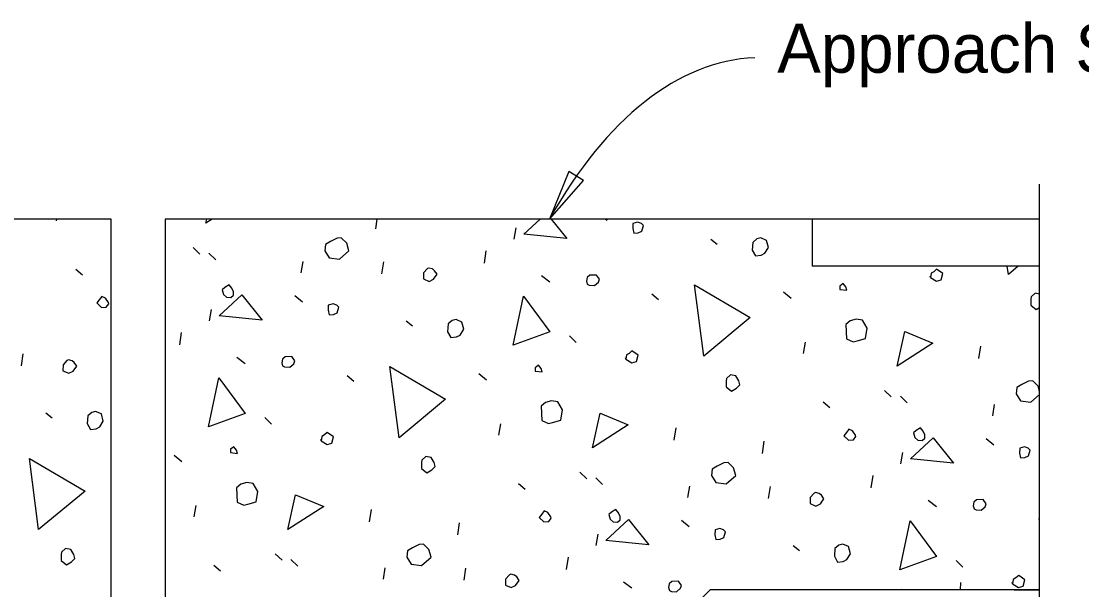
# Model space of a CAD drawing. Extents: x 0 to 30.8, y 0 to 21.2.
# Drawn here: x 25.516 to 28.795, y 17.529 to 19.286 of the extents above; entities that cross this region are included whole.
import ezdxf

# ---------------------------------------------------------------- set-up
doc = ezdxf.new("R2010")
doc.units = 0
for name, color, linetype in [('Dimension', 7, 'Continuous'), ('Miscellaneous', 7, 'Continuous'), ('SupstrConc', 7, 'Continuous'), ('TextStructures', 7, 'Continuous')]:
    doc.layers.add(name, color=color, linetype=linetype)

msp = doc.modelspace()

# ---------------------------------------------------------------- linework, layer by layer
at = {"layer": 'Dimension'}
msp.add_lwpolyline([(27.1495, 18.6746), (27.2542, 18.7936), (27.2091, 18.8214)], close=True, dxfattribs=at)
msp.add_lwpolyline([(28.6643, 15.7565), (28.6643, 16.023), (28.7418, 16.023), (28.6643, 16.0567), (28.5868, 16.0905), (28.6643, 16.0905), (28.6643, 18.7825)], dxfattribs=at)
msp.add_ellipse((27.8946, 16.8059), major_axis=(0.1111, -2.3674), ratio=0.464296, start_param=3.141604, end_param=3.781059, dxfattribs=at)
at = {"layer": 'Miscellaneous'}
for p, q in [((25.6248, 18.669), (25.6258, 18.6747)), ((26.6119, 18.6449), (26.6162, 18.6747)), ((27.3224, 18.6747), (27.327, 18.6708)), ((28.6643, 18.6747), (27.9607, 18.6747)), ((27.04, 18.612), (27.046, 18.6473)), ((27.6482, 18.612), (27.6679, 18.5965)), ((26.0477, 18.5869), (26.0686, 18.5666)), ((26.0965, 18.5689), (26.1175, 18.5486)), ((26.9484, 18.5383), (26.9539, 18.576)), ((26.3819, 18.5082), (26.388, 18.5435)), ((26.6312, 18.5051), (26.6366, 18.5428)), ((25.6855, 18.5196), (25.7058, 18.5018)), ((27.1243, 18.5001), (27.1501, 18.4811)), ((26.3619, 18.4381), (26.3853, 18.4185)), ((27.4655, 18.4439), (27.4858, 18.4261)), ((27.8729, 18.4496), (27.8963, 18.43)), ((26.0982, 18.3597), (26.1043, 18.395)), ((26.7064, 18.3596), (26.7261, 18.3442)), ((26.0066, 18.286), (26.0121, 18.3237)), ((27.2105, 18.3135), (27.2315, 18.2933)), ((27.9343, 18.259), (27.9404, 18.2943)), ((28.4767, 18.2439), (28.4821, 18.2815)), ((25.5171, 18.2209), (25.5225, 18.2586)), ((26.1825, 18.2477), (26.2083, 18.2287)), ((26.9311, 18.1972), (26.9545, 18.1776)), ((26.5237, 18.1916), (26.544, 18.1737)), ((28.1849, 18.145), (28.2058, 18.1247)), ((27.9951, 18.1096), (28.0154, 18.0918)), ((28.2337, 18.127), (28.2546, 18.1067)), ((28.5191, 18.0663), (28.5252, 18.1016)), ((25.5923, 18.0754), (25.612, 18.0599)), ((26.2688, 18.0612), (26.2897, 18.0409)), ((26.9925, 18.0066), (26.9986, 18.0419)), ((27.5349, 17.9915), (27.5404, 18.0292)), ((27.8073, 17.9506), (27.8127, 17.9883)), ((28.4991, 17.9962), (28.5225, 17.9766)), ((25.9893, 17.9449), (26.0127, 17.9253)), ((28.2354, 17.9178), (28.2415, 17.9531)), ((27.2431, 17.8926), (27.2641, 17.8723)), ((27.2919, 17.8746), (27.3129, 17.8544)), ((28.1438, 17.8441), (28.1493, 17.8818)), ((27.0533, 17.8573), (27.0736, 17.8394)), ((27.5773, 17.8139), (27.5834, 17.8492)), ((27.8266, 17.8109), (27.8321, 17.8485)), ((28.3197, 17.8058), (28.3455, 17.7868)), ((26.0508, 17.7543), (26.0568, 17.7896)), ((26.5932, 17.7392), (26.5986, 17.7769)), ((27.5573, 17.7439), (27.5807, 17.7242)), ((28.6609, 17.7497), (28.6643, 17.7467)), ((26.8655, 17.6983), (26.871, 17.736)), ((27.2936, 17.6654), (27.2997, 17.7007)), ((26.3013, 17.6403), (26.3223, 17.62)), ((27.9019, 17.6654), (27.9215, 17.6499)), ((26.3501, 17.6223), (26.3711, 17.602)), ((27.2021, 17.5917), (27.2075, 17.6294)), ((28.406, 17.6193), (28.4269, 17.599)), ((26.1115, 17.6049), (26.1318, 17.5871)), ((26.6356, 17.5616), (26.6416, 17.5969)), ((26.8849, 17.5585), (26.8903, 17.5962)), ((27.378, 17.5535), (27.4038, 17.5345)), ((28.5856, 17.5289), (28.6643, 17.5289))]:
    msp.add_line(p, q, dxfattribs=at)
for points in [[(26.087, 18.6621), (26.0898, 18.6747)], [(26.1067, 18.6747), (26.087, 18.6621)], [(27.0694, 18.6277), (27.12, 18.6747)], [(27.1545, 18.6747), (27.2025, 18.6142), (27.0694, 18.6277)], [(27.4063, 18.6455), (27.4102, 18.631), (27.4229, 18.6318), (27.4343, 18.6375), (27.4401, 18.6546), (27.4333, 18.6605), (27.4217, 18.6652), (27.4072, 18.6613), (27.4063, 18.6455)], [(26.4542, 18.5767), (26.4679, 18.5545), (26.5001, 18.5502), (26.5294, 18.5762), (26.5229, 18.6003), (26.5056, 18.6164), (26.4929, 18.6156), (26.4725, 18.6049), (26.4569, 18.5956), (26.4542, 18.5767)], [(27.7775, 18.6026), (27.7761, 18.5789), (27.7861, 18.5609), (27.8037, 18.563), (27.8151, 18.5687), (27.8257, 18.5871), (27.8199, 18.6088), (27.8022, 18.617), (27.7901, 18.6137), (27.7775, 18.6026)], [(26.7597, 18.5085), (26.7594, 18.4903), (26.7771, 18.4821), (26.791, 18.4884), (26.8022, 18.5043), (26.7942, 18.5151), (26.7874, 18.5211), (26.7765, 18.5233), (26.7716, 18.522), (26.7597, 18.5085)], [(28.5676, 18.5037), (28.5644, 18.5289)], [(28.5981, 18.5289), (28.5676, 18.5037)], [(27.2661, 18.4733), (27.2722, 18.4698), (27.288, 18.4689), (27.3005, 18.48), (27.3034, 18.4885), (27.2947, 18.5017), (27.2741, 18.5014), (27.2657, 18.494), (27.2635, 18.483), (27.2661, 18.4733)], [(28.327, 18.4936), (28.3453, 18.483), (28.3598, 18.4869), (28.365, 18.5064), (28.3459, 18.5194), (28.3376, 18.512), (28.3286, 18.507), (28.327, 18.4936), (28.3257, 18.4984)], [(26.1411, 18.4411), (26.1509, 18.4334), (26.1643, 18.4318), (26.1727, 18.4392), (26.1725, 18.4495), (26.1668, 18.4609), (26.1588, 18.4717), (26.1456, 18.463), (26.1372, 18.4556), (26.1411, 18.4411)], [(27.6258, 18.2514), (27.5978, 18.4716), (27.7699, 18.3702), (27.6258, 18.2514)], [(28.0468, 18.4574), (28.0681, 18.4553), (28.0655, 18.465), (28.0574, 18.4757), (28.0466, 18.4677), (28.0468, 18.4574)], [(25.7497, 18.4152), (25.7639, 18.4009), (25.779, 18.4024), (25.7868, 18.4122), (25.7855, 18.417), (25.7768, 18.4302), (25.7651, 18.4349), (25.7574, 18.425), (25.7497, 18.4152)], [(26.1276, 18.3754), (26.1981, 18.4408), (26.2607, 18.3618), (26.1276, 18.3754)], [(27.037, 18.2851), (27.069, 18.4361), (27.1503, 18.3259), (27.037, 18.2851)], [(28.6374, 18.4267), (28.6371, 18.4085), (28.6537, 18.3948), (28.6643, 18.4011)], [(28.6643, 18.4429), (28.6504, 18.4457), (28.6379, 18.4346), (28.6374, 18.4267)], [(26.4645, 18.3931), (26.4684, 18.3787), (26.4811, 18.3795), (26.4925, 18.3851), (26.4983, 18.4022), (26.4916, 18.4082), (26.48, 18.4128), (26.4655, 18.4089), (26.4645, 18.3931)], [(26.8358, 18.3503), (26.8343, 18.3266), (26.8443, 18.3086), (26.8619, 18.3107), (26.8733, 18.3163), (26.8839, 18.3347), (26.8781, 18.3564), (26.8604, 18.3646), (26.8483, 18.3614), (26.8358, 18.3503)], [(28.0656, 18.3485), (28.067, 18.3049), (28.0877, 18.2949), (28.0998, 18.2982), (28.1264, 18.3053), (28.1307, 18.3375), (28.1163, 18.3621), (28.0975, 18.3648), (28.0782, 18.3597), (28.0656, 18.3485)], [(28.2242, 18.2202), (28.2473, 18.3273), (28.3346, 18.2912), (28.2242, 18.2202)], [(27.3852, 18.2413), (27.4036, 18.2307), (27.4181, 18.2345), (27.4232, 18.254), (27.4042, 18.2671), (27.3958, 18.2596), (27.3868, 18.2546), (27.3852, 18.2413), (27.3839, 18.2461)], [(25.6456, 18.2242), (25.6453, 18.206), (25.663, 18.1979), (25.6769, 18.2042), (25.6881, 18.2201), (25.68, 18.2309), (25.6733, 18.2368), (25.6623, 18.2391), (25.6575, 18.2378), (25.6456, 18.2242)], [(26.3243, 18.221), (26.3304, 18.2175), (26.3462, 18.2165), (26.3588, 18.2276), (26.3616, 18.2362), (26.3529, 18.2494), (26.3323, 18.249), (26.3239, 18.2416), (26.3217, 18.2307), (26.3243, 18.221)], [(26.684, 17.999), (26.656, 18.2193), (26.8281, 18.1179), (26.684, 17.999)], [(27.105, 18.205), (27.1263, 18.2029), (27.1237, 18.2126), (27.1156, 18.2234), (27.1049, 18.2153), (27.105, 18.205)], [(26.0952, 18.0328), (26.1272, 18.1837), (26.2085, 18.0735), (26.0952, 18.0328)], [(27.6956, 18.1743), (27.6953, 18.1561), (27.7119, 18.1425), (27.7275, 18.1518), (27.7376, 18.1623), (27.7344, 18.1744), (27.7251, 18.19), (27.7086, 18.1933), (27.6961, 18.1822), (27.6956, 18.1743)], [(28.6643, 18.1429), (28.6601, 18.1584), (28.6428, 18.1745), (28.6301, 18.1737), (28.6097, 18.163), (28.5941, 18.1537), (28.5913, 18.1348)], [(28.5913, 18.1348), (28.6051, 18.1126), (28.6373, 18.1083), (28.6643, 18.1322)], [(27.1238, 18.0962), (27.1252, 18.0525), (27.146, 18.0426), (27.158, 18.0458), (27.1846, 18.0529), (27.1889, 18.0851), (27.1746, 18.1098), (27.1557, 18.1125), (27.1364, 18.1073), (27.1238, 18.0962)], [(25.7216, 18.066), (25.7202, 18.0424), (25.7302, 18.0243), (25.7478, 18.0264), (25.7592, 18.0321), (25.7698, 18.0505), (25.764, 18.0722), (25.7462, 18.0804), (25.7342, 18.0772), (25.7216, 18.066)], [(27.2825, 17.9679), (27.3055, 18.075), (27.3928, 18.0388), (27.2825, 17.9679)], [(26.4434, 17.9889), (26.4618, 17.9783), (26.4763, 17.9822), (26.4814, 18.0017), (26.4624, 18.0147), (26.454, 18.0073), (26.445, 18.0023), (26.4434, 17.9889), (26.4421, 17.9937)], [(28.0593, 18.0052), (28.0735, 17.9909), (28.0886, 17.9923), (28.0963, 18.0022), (28.095, 18.007), (28.0863, 18.0202), (28.0747, 18.0248), (28.067, 18.015), (28.0593, 18.0052)], [(28.2648, 17.9334), (28.3353, 17.9989), (28.3979, 17.9199), (28.2648, 17.9334)], [(28.2783, 17.9992), (28.2881, 17.9914), (28.3015, 17.9899), (28.3099, 17.9973), (28.3097, 18.0076), (28.304, 18.019), (28.296, 18.0298), (28.2828, 18.0211), (28.2744, 18.0137), (28.2783, 17.9992)], [(26.1633, 17.9527), (26.1845, 17.9506), (26.1819, 17.9603), (26.1739, 17.971), (26.1631, 17.963), (26.1633, 17.9527)], [(28.6017, 17.9512), (28.6056, 17.9368), (28.6183, 17.9376), (28.6297, 17.9432), (28.6355, 17.9603), (28.6288, 17.9662), (28.6172, 17.9709), (28.6027, 17.967), (28.6017, 17.9512)], [(25.5699, 17.7148), (25.5419, 17.9351), (25.714, 17.8336), (25.5699, 17.7148)], [(26.7538, 17.922), (26.7535, 17.9038), (26.7701, 17.8901), (26.7857, 17.8995), (26.7959, 17.9099), (26.7926, 17.922), (26.7833, 17.9376), (26.7668, 17.941), (26.7543, 17.9299), (26.7538, 17.922)], [(27.6496, 17.8825), (27.6633, 17.8603), (27.6955, 17.8559), (27.7248, 17.8819), (27.7183, 17.9061), (27.7011, 17.9221), (27.6883, 17.9213), (27.6679, 17.9107), (27.6523, 17.9013), (27.6496, 17.8825)], [(26.1821, 17.8438), (26.1834, 17.8002), (26.2042, 17.7902), (26.2163, 17.7935), (26.2428, 17.8006), (26.2471, 17.8328), (26.2328, 17.8574), (26.2139, 17.8601), (26.1946, 17.855), (26.1821, 17.8438)], [(26.3407, 17.7155), (26.3637, 17.8226), (26.4511, 17.7865), (26.3407, 17.7155)], [(27.9551, 17.8142), (27.9548, 17.796), (27.9726, 17.7878), (27.9864, 17.7941), (27.9977, 17.8101), (27.9896, 17.8209), (27.9828, 17.8268), (27.9719, 17.8291), (27.967, 17.8278), (27.9551, 17.8142)], [(28.4615, 17.7791), (28.4676, 17.7755), (28.4834, 17.7746), (28.4959, 17.7857), (28.4988, 17.7943), (28.4901, 17.8075), (28.4695, 17.8071), (28.4611, 17.7997), (28.4589, 17.7887), (28.4615, 17.7791)], [(27.1175, 17.7528), (27.1317, 17.7385), (27.1468, 17.74), (27.1545, 17.7498), (27.1532, 17.7546), (27.1445, 17.7678), (27.1329, 17.7725), (27.1252, 17.7627), (27.1175, 17.7528)], [(27.3365, 17.7468), (27.3463, 17.7391), (27.3597, 17.7375), (27.3681, 17.7449), (27.3679, 17.7552), (27.3623, 17.7667), (27.3542, 17.7774), (27.341, 17.7687), (27.3326, 17.7613), (27.3365, 17.7468)], [(27.3231, 17.6811), (27.3935, 17.7466), (27.4561, 17.6676), (27.3231, 17.6811)], [(28.2324, 17.5909), (28.2644, 17.7418), (28.3457, 17.6316), (28.2324, 17.5909)], [(27.6599, 17.6989), (27.6638, 17.6844), (27.6765, 17.6852), (27.688, 17.6909), (27.6937, 17.7079), (27.687, 17.7139), (27.6754, 17.7186), (27.6609, 17.7147), (27.6599, 17.6989)], [(25.6397, 17.6377), (25.6394, 17.6195), (25.656, 17.6059), (25.6716, 17.6152), (25.6817, 17.6257), (25.6785, 17.6378), (25.6691, 17.6534), (25.6527, 17.6568), (25.6402, 17.6456), (25.6397, 17.6377)], [(26.7078, 17.6301), (26.7215, 17.6079), (26.7537, 17.6036), (26.783, 17.6296), (26.7765, 17.6537), (26.7593, 17.6698), (26.7466, 17.669), (26.7261, 17.6583), (26.7105, 17.649), (26.7078, 17.6301)], [(28.0312, 17.656), (28.0298, 17.6323), (28.0398, 17.6143), (28.0573, 17.6164), (28.0687, 17.6221), (28.0794, 17.6405), (28.0735, 17.6622), (28.0558, 17.6704), (28.0437, 17.6671), (28.0312, 17.656)], [(27.0134, 17.5619), (27.0131, 17.5437), (27.0308, 17.5355), (27.0446, 17.5418), (27.0559, 17.5577), (27.0478, 17.5685), (27.0411, 17.5745), (27.0301, 17.5767), (27.0253, 17.5754), (27.0134, 17.5619)], [(28.5806, 17.547), (28.599, 17.5364), (28.6135, 17.5403), (28.6186, 17.5598), (28.5996, 17.5728), (28.5912, 17.5654), (28.5822, 17.5604), (28.5806, 17.547), (28.5793, 17.5518)], [(27.5197, 17.5267), (27.5258, 17.5232), (27.5416, 17.5222), (27.5542, 17.5334), (27.5571, 17.5419), (27.5483, 17.5551), (27.5277, 17.5548), (27.5194, 17.5473), (27.5171, 17.5364), (27.5197, 17.5267)], [(28.4193, 17.5511), (28.4186, 17.5289)], [(28.2378, 17.5289), (28.2376, 17.5299), (28.2353, 17.5289)], [(28.3112, 17.5289), (28.3111, 17.5291), (28.3108, 17.5289)]]:
    msp.add_lwpolyline(points, dxfattribs=at)
at = {"layer": 'SupstrConc'}
for p, q in [((25.794, 18.6747), (21.0171, 18.6747)), ((25.794, 16.8413), (25.794, 18.6747)), ((27.9607, 18.6747), (25.9607, 18.6747)), ((25.9607, 18.6747), (25.9607, 17.2997)), ((27.9607, 18.6747), (27.9607, 18.5289)), ((28.6643, 18.5289), (27.9607, 18.5289)), ((27.4607, 17.3442), (27.6454, 17.5289)), ((28.6643, 17.5289), (27.6454, 17.5289))]:
    msp.add_line(p, q, dxfattribs=at)

# ---------------------------------------------------------------- texts
at = {"layer": 'TextStructures'}
msp.add_text('Approach Slab', height=0.1512, dxfattribs=at).set_placement((27.8531, 19.1268))

doc.saveas('drawing.dxf')
